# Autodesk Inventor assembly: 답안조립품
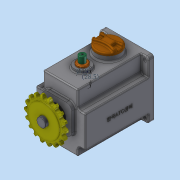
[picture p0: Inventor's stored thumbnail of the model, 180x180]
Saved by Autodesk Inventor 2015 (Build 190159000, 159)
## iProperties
Created: 2017-12
Part Number: 답안조립품
Document SubType Name: Assembly
Designer: SCD-A03
Mass: 2726.6 g
Surface Area: 2015.6 cm^2
Volume: 734.132 cm^3
Density: 3.71404 g/cm^3
Author: SCD-A03
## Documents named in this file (17)
- C:\Users\SCD-A03\Desktop\371207V1032\답안조립품.iam
- C:\Users\SCD-A03\Desktop\371207V1032\본체.ipt
- C:\Users\SCD-A03\Desktop\371207V1032\멈춤나사 M3x8.ipt
- C:\Users\SCD-A03\Desktop\371207V1032\메인축.ipt
- C:\Users\SCD-A03\Desktop\371207V1032\베어링 608.ipt
- C:\Users\SCD-A03\Desktop\371207V1032\베어링 6003.ipt
- C:\Users\SCD-A03\Desktop\371207V1032\볼트 M4 x 10.ipt
- C:\Users\SCD-A03\Desktop\371207V1032\부시.ipt
- C:\Users\SCD-A03\Desktop\371207V1032\상부 캡.ipt
- C:\Users\SCD-A03\Desktop\371207V1032\서브축.ipt
- C:\Users\SCD-A03\Desktop\371207V1032\스프로킷.ipt
- C:\Users\SCD-A03\Desktop\371207V1032\슬라이더.ipt
- C:\Users\SCD-A03\Desktop\371207V1032\오일 실 8 22 7.ipt
- C:\Users\SCD-A03\Desktop\371207V1032\오일 실 17 32 8.ipt
- C:\Users\SCD-A03\Desktop\371207V1032\커버.ipt
- C:\Users\SCD-A03\Desktop\371207V1032\키 5 x 5 x 18.ipt
- C:\Users\SCD-A03\Desktop\371207V1032\가변스프링.ipt
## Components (1 placed, 1 different names)
1. 가변스프링:1
